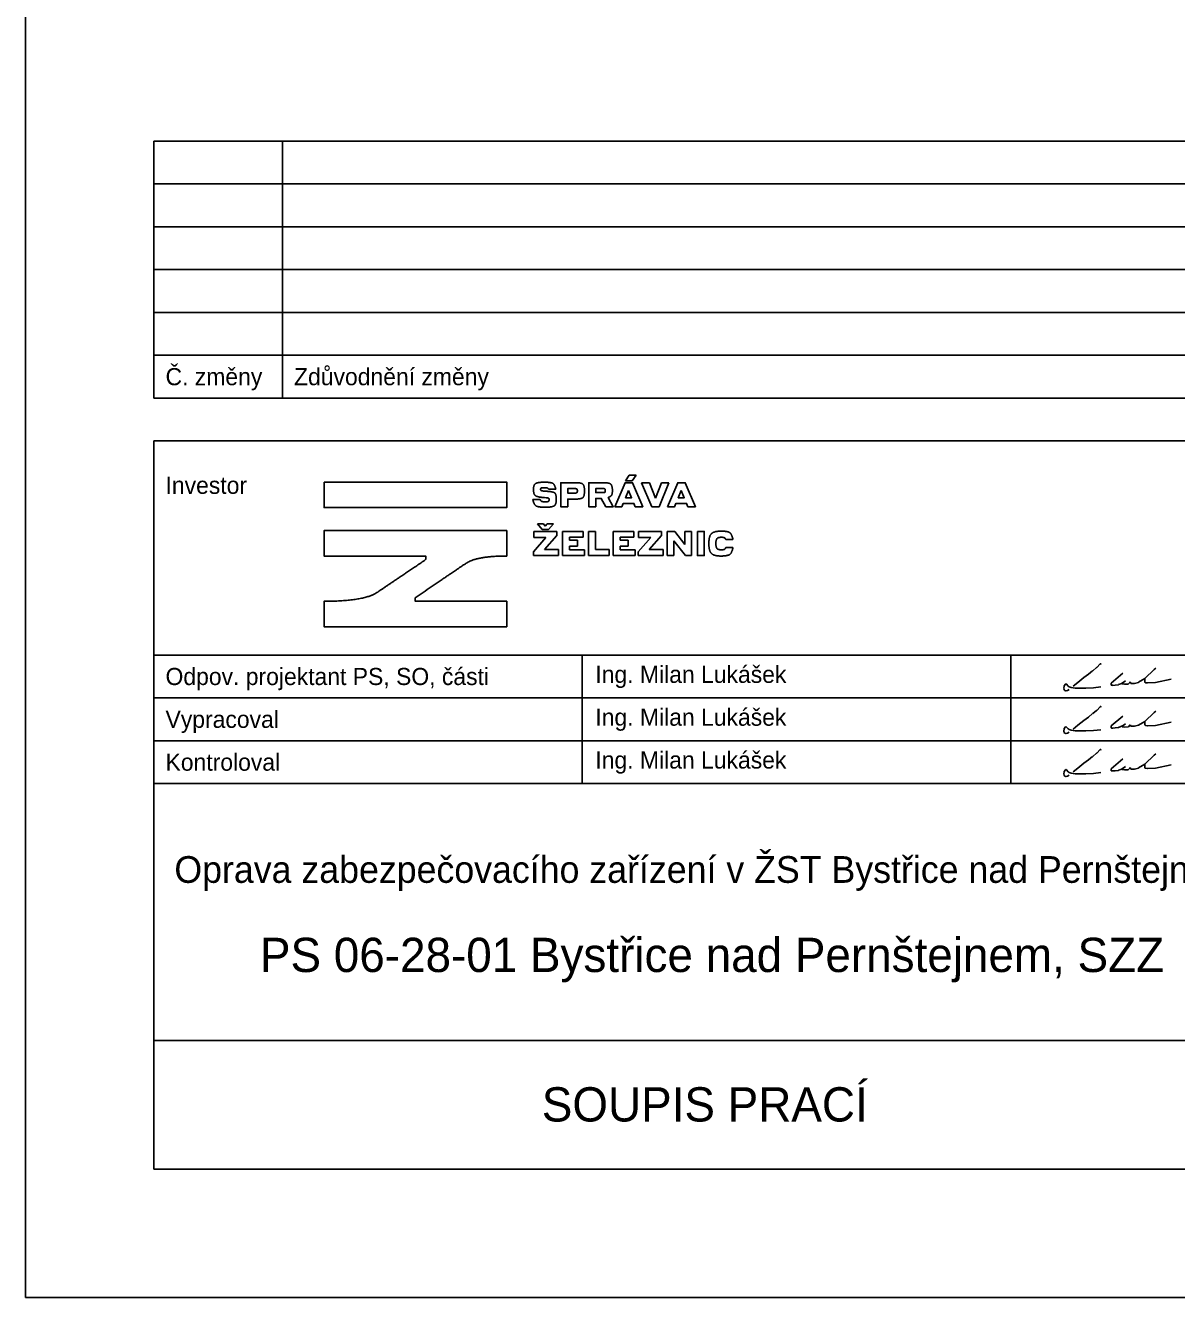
# Model space of a CAD drawing. Extents: x -789421 to -789211, y -987399 to -987102.
# Drawn here: x -789420.6 to -789286.2, y -987398.6 to -987250.1 of the extents above; entities that cross this region are included whole.
import ezdxf

# ---------------------------------------------------------------- set-up
doc = ezdxf.new("R2010")
doc.units = 0
for name, color, linetype in [('Deska žb', 7, 'Continuous'), ('logo_sprava_zeleznic', 7, 'Continuous'), ('Nová vrstva (0)', 7, 'Continuous'), ('Ramečky', 7, 'Continuous'), ('Rámečky-tisk', 7, 'Continuous'), ('Text', 7, 'Continuous'), ('Text barevný', 7, 'Continuous')]:
    doc.layers.add(name, color=color, linetype=linetype)

# ---------------------------------------------------------------- blocks, each defined once
blk = doc.blocks.new('Lukášek')
at = {"layer": 'Deska žb'}
for points in [[(-800, 511), (-947, 387)], [(-658, 623), (-799, 512)], [(-538, 757), (-656, 625)], [(-526, 763), (-532, 761)], [(-502, 743), (-503, 750)], [(1060, 236), (1392, 554)], [(1393, 555), (1452, 601)], [(-1810, -20), (-1764, 37)], [(-1741, 39), (-1734, 34)], [(-1733, 32), (-1676, -31)], [(-1334, 99), (-1493, -40)], [(-1120, 270), (-1334, 99)], [(-949, 386), (-1119, 271)], [(-146, 58), (-146, 41)], [(-146, 38), (-141, 12)], [(277, 422), (-140, 71)], [(0, 0), (116, 16)], [(120, 17), (203, 49)], [(205, 50), (283, 92)], [(244, 59), (250, 49)], [(261, 42), (331, 30)], [(284, 93), (373, 148)], [(335, 30), (465, 39)], [(476, 45), (519, 96)], [(546, 94), (559, 68)], [(574, 60), (681, 63)], [(685, 63), (829, 98)], [(833, 100), (1057, 233)], [(1056, 231), (1056, 130)], [(1058, 121), (1075, 95)], [(1086, 88), (1147, 79)], [(1150, 79), (1434, 92)], [(1437, 93), (1997, 211)], [(-1825, -119), (-1813, -28)], [(-1809, -179), (-1825, -126)], [(-1757, -200), (-1797, -190)], [(-1700, -189), (-1749, -201)], [(-1634, -152), (-1695, -187)], [(-1672, -34), (-1636, -56)], [(-1633, -57), (-1570, -82)], [(-1567, -83), (-1418, -106)], [(-1415, -106), (-1252, -106), (-1041, -106)], [(-1040, -106), (-770, -93)], [(-769, -92), (-512, -66)], [(-127, -2), (-88, -6)], [(-85, -7), (-1, 0)]]:
    blk.add_lwpolyline(points, dxfattribs=at)
for centre, start, end in [((-789, 499), 128.3333, 130.1792), ((-669, 636), 308.3333, 317.9357), ((-525, 746), 113.9625, 137.9357), ((-519, 748), 6.3402, 113.9625), ((1403, 542), 127.875, 133.8427), ((-1751, 26), 50.1944, 140.7106), ((-1745, 21), 41.9872, 50.1944), ((-1324, 86), 128.6598, 131.1859), ((-1110, 257), 123.9436, 128.6598), ((-958, 399), 303.9436, 310.1792), ((-129, 58), 130.156, 180), ((-129, 41), 180, 189.4623), ((-125, 15), 189.4623, 262.875), ((-2, 16), 274.3987, 277.9072), ((114, 32), 277.9072, 291.0375), ((197, 64), 291.0375, 298.4429), ((264, 58), 210.9638, 260.5377), ((275, 107), 298.4429, 302.1957), ((334, 46), 260.5377, 274.0856), ((463, 55), 274.0856, 320.4403), ((531, 86), 27.8973, 140.4403), ((574, 76), 207.8973, 271.5911), ((681, 79), 271.5911, 283.7363), ((825, 114), 283.7363, 300.7189), ((1072, 130), 180, 212.4712), ((1049, 247), 300.7189, 313.8427), ((1089, 104), 212.4712, 261.8699), ((1149, 96), 261.8699, 272.6324), ((1433, 109), 272.6324, 281.9566), ((-1809, -121), 172.4054, 196.6992), ((-1797, -30), 140.7106, 172.4054), ((-1793, -175), 196.6992, 255.9638), ((-1753, -184), 255.9638, 283.2405), ((-1703, -173), 283.2405, 300.0686), ((-1664, -20), 221.9872, 239.7436), ((-1627, -41), 239.7436, 248.1986), ((-1564, -67), 248.1986, 261.3475), ((-1415, -89), 261.3475, 270), ((-1041, -89), 270, 272.7927), ((-771, -76), 272.7927, 275.856), ((-86, 10), 262.875, 274.3987)]:
    blk.add_arc(centre, 16.5, start, end, dxfattribs=at)

msp = doc.modelspace()

# ---------------------------------------------------------------- linework, layer by layer
at = {"layer": 'logo_sprava_zeleznic'}
for p, q in [((-789350.56, -987303.26), (-789350.12, -987302.6)), ((-789349.78, -987303.26), (-789350.56, -987303.26)), ((-789350.12, -987302.6), (-789349.3, -987302.6)), ((-789349.3, -987302.6), (-789349.78, -987303.26)), ((-789348.7, -987303.48), (-789347.76, -987303.48)), ((-789347.49, -987306.29), (-789348.7, -987303.48)), ((-789347.76, -987303.48), (-789347.05, -987305.28)), ((-789347.05, -987305.28), (-789346.34, -987303.48)), ((-789345.49, -987303.48), (-789346.64, -987306.29)), ((-789346.34, -987303.48), (-789345.49, -987303.48)), ((-789359.76, -987304.48), (-789360.15, -987304.45)), ((-789359.51, -987304.23), (-789358.69, -987304.23)), ((-789360.51, -987305.45), (-789361.36, -987305.45)), ((-789346.64, -987306.29), (-789347.49, -987306.29)), ((-789361.26, -987309.17), (-789358.55, -987309.17)), ((-789361.26, -987309.86), (-789361.26, -987309.17)), ((-789360.29, -987308.96), (-789360.83, -987308.28)), ((-789360.83, -987308.28), (-789360.14, -987308.28)), ((-789359.53, -987308.96), (-789360.29, -987308.96)), ((-789360.14, -987308.28), (-789359.91, -987308.56)), ((-789358.55, -987309.63), (-789360.02, -987311.29)), ((-789359.91, -987308.56), (-789359.68, -987308.28)), ((-789359.68, -987308.28), (-789358.97, -987308.28)), ((-789358.97, -987308.28), (-789359.53, -987308.96)), ((-789358.55, -987309.17), (-789358.55, -987309.63)), ((-789357.92, -987309.17), (-789355.49, -987309.17)), ((-789357.92, -987311.99), (-789357.92, -987309.17)), ((-789355.49, -987309.17), (-789355.49, -987309.83)), ((-789354.86, -987309.17), (-789354.05, -987309.17)), ((-789354.86, -987311.99), (-789354.86, -987309.17)), ((-789354.05, -987309.17), (-789354.05, -987311.28)), ((-789351.99, -987309.17), (-789349.57, -987309.17)), ((-789351.99, -987311.99), (-789351.99, -987309.17)), ((-789349.57, -987309.17), (-789349.57, -987309.83)), ((-789349.03, -987309.17), (-789346.33, -987309.17)), ((-789349.03, -987309.86), (-789349.03, -987309.17)), ((-789346.33, -987309.63), (-789347.8, -987311.29)), ((-789346.33, -987309.17), (-789346.33, -987309.63)), ((-789345.69, -987309.17), (-789344.78, -987309.17)), ((-789345.69, -987311.99), (-789345.69, -987309.17)), ((-789344.78, -987309.17), (-789343.63, -987310.68)), ((-789343.63, -987310.68), (-789343.63, -987309.17)), ((-789343.63, -987309.17), (-789342.85, -987309.17)), ((-789342.85, -987309.17), (-789342.85, -987311.99)), ((-789361.3, -987311.53), (-789359.84, -987309.86)), ((-789359.84, -987309.86), (-789361.26, -987309.86)), ((-789355.49, -987309.83), (-789357.1, -987309.83)), ((-789357.1, -987309.83), (-789357.1, -987310.2)), ((-789357.1, -987310.2), (-789356.14, -987310.2)), ((-789356.14, -987310.87), (-789357.1, -987310.87)), ((-789357.1, -987310.87), (-789357.1, -987311.3)), ((-789356.14, -987310.2), (-789356.14, -987310.87)), ((-789349.57, -987309.83), (-789351.18, -987309.83)), ((-789351.18, -987309.83), (-789351.18, -987310.2)), ((-789351.18, -987310.2), (-789350.22, -987310.2)), ((-789350.22, -987310.87), (-789351.18, -987310.87)), ((-789351.18, -987310.87), (-789351.18, -987311.3)), ((-789350.22, -987310.2), (-789350.22, -987310.87)), ((-789349.07, -987311.53), (-789347.61, -987309.86)), ((-789347.61, -987309.86), (-789349.03, -987309.86)), ((-789343.53, -987311.99), (-789344.89, -987310.26)), ((-789344.89, -987310.26), (-789344.89, -987311.99)), ((-789338.84, -987310.12), (-789338.01, -987310.12)), ((-789338.01, -987311.05), (-789338.83, -987311.05)), ((-789361.3, -987311.99), (-789361.3, -987311.53)), ((-789358.39, -987311.99), (-789361.3, -987311.99)), ((-789360.02, -987311.29), (-789358.39, -987311.29)), ((-789358.39, -987311.29), (-789358.39, -987311.99)), ((-789355.34, -987311.99), (-789357.92, -987311.99)), ((-789357.1, -987311.3), (-789355.34, -987311.3)), ((-789355.34, -987311.3), (-789355.34, -987311.99)), ((-789352.47, -987311.99), (-789354.86, -987311.99)), ((-789354.05, -987311.28), (-789352.47, -987311.28)), ((-789352.47, -987311.28), (-789352.47, -987311.99)), ((-789349.41, -987311.99), (-789351.99, -987311.99)), ((-789351.18, -987311.3), (-789349.41, -987311.3)), ((-789349.41, -987311.3), (-789349.41, -987311.99)), ((-789349.07, -987311.99), (-789349.07, -987311.53)), ((-789346.16, -987311.99), (-789349.07, -987311.99)), ((-789347.8, -987311.29), (-789346.16, -987311.29)), ((-789346.16, -987311.29), (-789346.16, -987311.99)), ((-789344.89, -987311.99), (-789345.69, -987311.99)), ((-789342.85, -987311.99), (-789343.53, -987311.99))]:
    msp.add_line(p, q, dxfattribs=at)
for points in [[(-789385.73, -987303.4), (-789364.41, -987303.4), (-789364.41, -987306.38), (-789385.73, -987306.38)], [(-789351.8, -987306.29), (-789350.98, -987306.29), (-789350.82, -987305.89), (-789349.57, -987305.89), (-789349.41, -987306.29), (-789348.53, -987306.29), (-789349.73, -987303.48), (-789350.6, -987303.48)], [(-789345.65, -987306.29), (-789344.83, -987306.29), (-789344.66, -987305.89), (-789343.42, -987305.89), (-789343.26, -987306.29), (-789342.38, -987306.29), (-789343.57, -987303.48), (-789344.45, -987303.48)], [(-789350.19, -987304.39), (-789349.85, -987305.23), (-789350.54, -987305.23)], [(-789344.04, -987304.39), (-789343.7, -987305.23), (-789344.39, -987305.23)], [(-789342.16, -987309.17), (-789341.35, -987309.17), (-789341.35, -987311.99), (-789342.16, -987311.99)]]:
    msp.add_lwpolyline(points, close=True, dxfattribs=at)
for points in [[(-789356.38, -987303.48), (-789358.11, -987303.48), (-789358.11, -987306.29), (-789357.3, -987306.29), (-789357.3, -987305.39), (-789356.38, -987305.39)], [(-789353.12, -987303.48), (-789354.84, -987303.48), (-789354.84, -987306.29), (-789354.03, -987306.29), (-789354.03, -987305.31), (-789353.39, -987305.31), (-789352.84, -987306.29), (-789351.98, -987306.29), (-789352.59, -987305.22)], [(-789356.48, -987304.69), (-789357.3, -987304.69), (-789357.3, -987304.17), (-789356.48, -987304.17)], [(-789353.22, -987304.64), (-789354.03, -987304.64), (-789354.03, -987304.16), (-789353.22, -987304.16)], [(-789373.87, -987312.46), (-789373.87, -987312.04), (-789385.73, -987312.04), (-789385.73, -987309.07), (-789364.41, -987309.07), (-789364.41, -987312.04)], [(-789375.1, -987316.91), (-789375.1, -987317.32), (-789364.41, -987317.32), (-789364.41, -987320.3), (-789385.73, -987320.3), (-789385.73, -987317.32), (-789385.71, -987317.32)]]:
    msp.add_lwpolyline(points, dxfattribs=at)
for centre, radius, start, end in [((-789361.9, -987326.14), 21.01, 84.2634, 85.3384), ((-789411.18, -987259.6), 64.69, 304.0901, 305.2133), ((-789074.63, -987753.54), 530.02, 124.292, 124.5333)]:
    msp.add_arc(centre, radius, start, end, dxfattribs=at)
for points in [[(-789360.05, -987303.42), (-789360.77, -987303.42), (-789361.29, -987303.71), (-789361.29, -987304.28)], [(-789358.69, -987304.23), (-789358.77, -987303.87), (-789359.09, -987303.42), (-789360.05, -987303.42)], [(-789355.34, -987304.43), (-789355.34, -987303.8), (-789355.73, -987303.48), (-789356.38, -987303.48)], [(-789352.08, -987304.4), (-789352.08, -987303.79), (-789352.49, -987303.48), (-789353.12, -987303.48)], [(-789361.29, -987304.28), (-789361.29, -987304.83), (-789360.87, -987305.14), (-789360.19, -987305.2)], [(-789360.46, -987304.24), (-789360.46, -987304.12), (-789360.3, -987304.06), (-789360.05, -987304.06)], [(-789360.15, -987304.45), (-789360.35, -987304.43), (-789360.46, -987304.36), (-789360.46, -987304.24)], [(-789360.05, -987304.06), (-789359.73, -987304.06), (-789359.55, -987304.17), (-789359.51, -987304.23)], [(-789358.63, -987305.4), (-789358.63, -987304.79), (-789359.03, -987304.53), (-789359.76, -987304.48)], [(-789356.48, -987304.17), (-789356.27, -987304.17), (-789356.17, -987304.26), (-789356.17, -987304.43)], [(-789356.17, -987304.43), (-789356.17, -987304.59), (-789356.27, -987304.69), (-789356.48, -987304.69)], [(-789356.38, -987305.39), (-789355.73, -987305.39), (-789355.34, -987305.06), (-789355.34, -987304.43)], [(-789353.22, -987304.16), (-789353.02, -987304.16), (-789352.91, -987304.23), (-789352.91, -987304.4)], [(-789352.91, -987304.4), (-789352.91, -987304.55), (-789353.02, -987304.64), (-789353.22, -987304.64)], [(-789352.59, -987305.22), (-789352.27, -987305.08), (-789352.08, -987304.8), (-789352.08, -987304.4)], [(-789361.36, -987305.45), (-789361.29, -987305.84), (-789360.93, -987306.34), (-789359.92, -987306.34)], [(-789359.92, -987305.71), (-789360.28, -987305.71), (-789360.46, -987305.57), (-789360.51, -987305.45)], [(-789359.92, -987306.34), (-789359.08, -987306.34), (-789358.63, -987306), (-789358.63, -987305.4)], [(-789359.47, -987305.46), (-789359.47, -987305.61), (-789359.6, -987305.71), (-789359.92, -987305.71)], [(-789359.8, -987305.23), (-789359.6, -987305.26), (-789359.47, -987305.31), (-789359.47, -987305.46)], [(-789339.36, -987309.13), (-789340.22, -987309.13), (-789340.82, -987309.73), (-789340.82, -987310.58)], [(-789338.01, -987310.12), (-789338.06, -987309.8), (-789338.4, -987309.13), (-789339.36, -987309.13)], [(-789340.82, -987310.58), (-789340.82, -987311.43), (-789340.22, -987312.04), (-789339.36, -987312.04)], [(-789340, -987310.58), (-789340, -987310.18), (-789339.76, -987309.85), (-789339.36, -987309.85)], [(-789339.36, -987311.31), (-789339.76, -987311.31), (-789340, -987310.99), (-789340, -987310.58)], [(-789339.36, -987309.85), (-789339.02, -987309.85), (-789338.88, -987310.05), (-789338.84, -987310.12)], [(-789339.36, -987312.04), (-789338.37, -987312.04), (-789338.05, -987311.31), (-789338.01, -987311.05)], [(-789338.83, -987311.05), (-789338.87, -987311.12), (-789339.02, -987311.31), (-789339.36, -987311.31)], [(-789364.41, -987312.04), (-789367.9, -987312.04), (-789370.38, -987313.71), (-789373.25, -987315.65)], [(-789385.71, -987317.32), (-789381.06, -987317.31), (-789378.08, -987315.3), (-789374.92, -987313.18)]]:
    msp.add_open_spline(points, degree=2, dxfattribs=at)
at = {"layer": 'Ramečky'}
for p, q in [((-789225.59, -987263.6), (-789405.59, -987263.6)), ((-789405.59, -987263.6), (-789405.59, -987293.6)), ((-789390.59, -987263.6), (-789390.59, -987293.6)), ((-789255.59, -987268.6), (-789405.59, -987268.6)), ((-789255.59, -987273.6), (-789405.59, -987273.6)), ((-789255.59, -987278.6), (-789405.59, -987278.6)), ((-789255.59, -987283.6), (-789405.59, -987283.6)), ((-789255.59, -987288.6), (-789405.59, -987288.6)), ((-789225.59, -987293.6), (-789405.59, -987293.6)), ((-789225.59, -987298.6), (-789405.59, -987298.6)), ((-789405.59, -987383.6), (-789405.59, -987298.6)), ((-789405.59, -987323.6), (-789275.59, -987323.6)), ((-789405.59, -987328.6), (-789275.59, -987328.6)), ((-789405.59, -987333.6), (-789275.59, -987333.6)), ((-789405.59, -987338.6), (-789275.59, -987338.6)), ((-789405.59, -987368.6), (-789225.59, -987368.6)), ((-789405.59, -987383.6), (-789225.59, -987383.6))]:
    msp.add_line(p, q, dxfattribs=at)
for points in [[(-789355.59, -987323.6), (-789355.59, -987338.6)], [(-789305.59, -987323.6), (-789305.59, -987338.6)]]:
    msp.add_lwpolyline(points, dxfattribs=at)
at = {"layer": 'Rámečky-tisk'}
msp.add_line((-789420.59, -987101.6), (-789420.59, -987398.6), dxfattribs=at)
msp.add_lwpolyline([(-789420.59, -987398.6), (-789210.59, -987398.6), (-789210.59, -987101.6)], dxfattribs=at)

# ---------------------------------------------------------------- block references
at = {"layer": 'Nová vrstva (0)', "xscale": 0.00327555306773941, "yscale": 0.00327555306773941}
for p in [(-789293.4, -987327.11), (-789293.4, -987332.11), (-789293.4, -987337.11)]:
    msp.add_blockref('Lukášek', p, dxfattribs=at)

# ---------------------------------------------------------------- texts
at = {"layer": 'Text'}
for s, p in [('Č. změny', (-789404.24, -987292.1)), ('Zdůvodnění změny', (-789389.24, -987292.1)), ('Investor', (-789404.24, -987304.78)), ('Odpov. projektant PS, SO, části', (-789404.24, -987327.1)), ('Ing. Milan Lukášek', (-789354.07, -987326.85)), ('Vypracoval', (-789404.24, -987332.1)), ('Ing. Milan Lukášek', (-789354.07, -987331.85)), ('Ing. Milan Lukášek', (-789354.07, -987336.85)), ('Kontroloval', (-789404.24, -987337.1))]:
    msp.add_text(s, height=2, dxfattribs=at).set_placement(p)
at = {"layer": 'Text barevný'}
for s, height, p in [('Oprava zabezpečovacího zařízení v ŽST Bystřice nad Pernštejnem', 3.1179, (-789403.21, -987350.19)), ('PS 06-28-01 Bystřice nad Pernštejnem, SZZ', 4, (-789393.22, -987360.6)), ('SOUPIS PRACÍ', 4, (-789360.32, -987378.05))]:
    msp.add_text(s, height=height, dxfattribs=at).set_placement(p)

doc.saveas('drawing.dxf')
